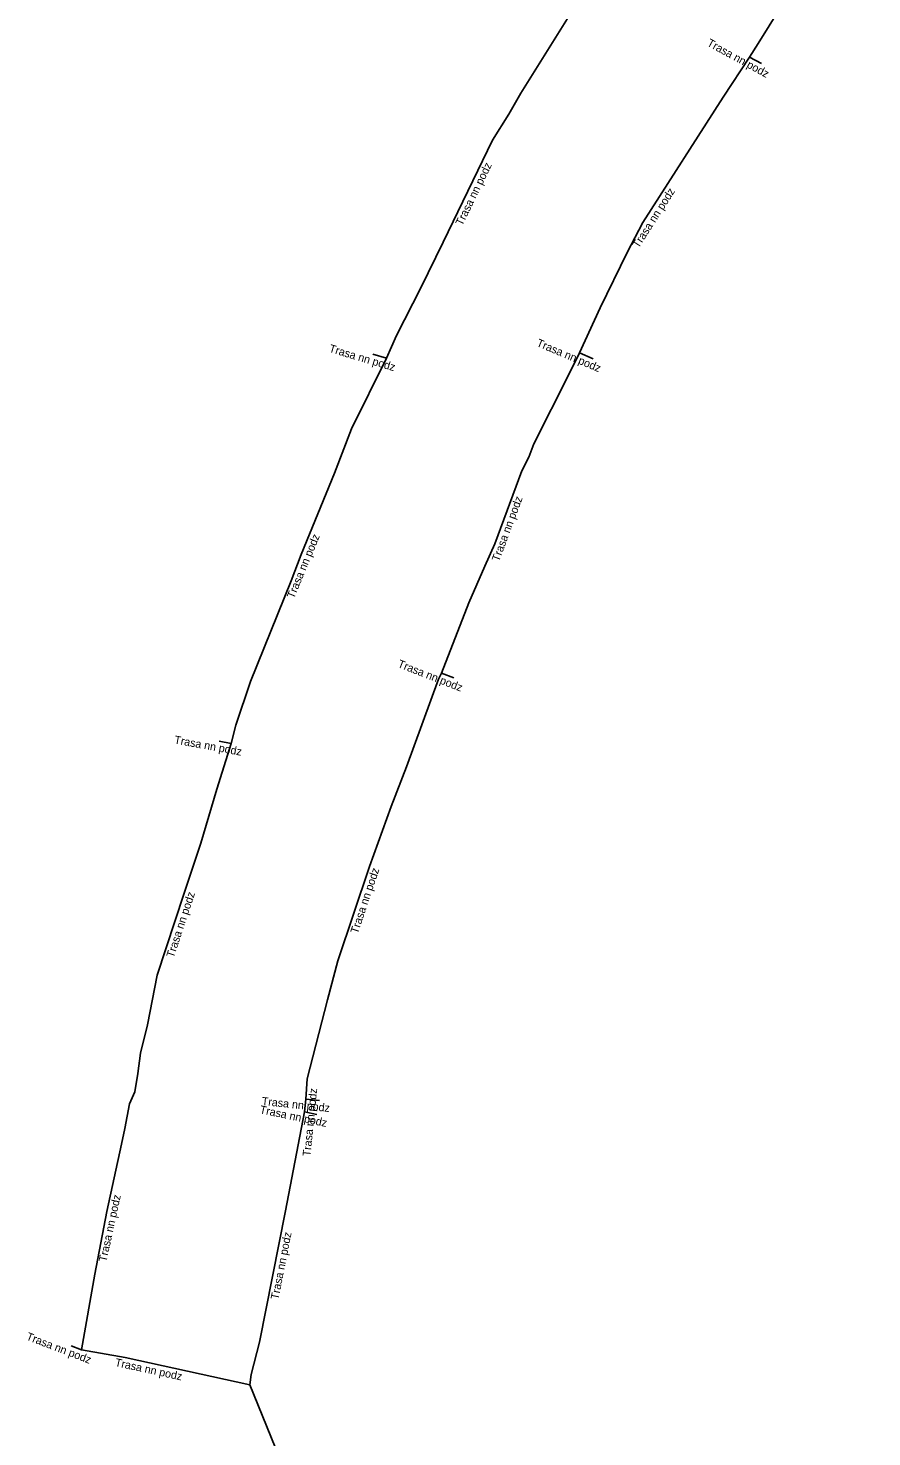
# Model space of a CAD drawing. Extents: x -756855 to -756032, y -1046964 to -1046550.
# Drawn here: x -756693.7 to -756641, y -1046811.5 to -1046723.5 of the extents above; entities that cross this region are included whole.
import ezdxf

# ---------------------------------------------------------------- set-up
doc = ezdxf.new("R2010")
doc.units = 0
doc.layers.add('Popiskový text - Ostatní atributy Trasy', color=7, linetype='Continuous')
doc.layers.add('Spojnice NN', color=7, linetype='Continuous')

msp = doc.modelspace()

# ---------------------------------------------------------------- linework, layer by layer
at = {"layer": 'Spojnice NN'}
for points in [[(-756648.65, -1046725.33), (-756648.11, -1046724.48), (-756646.73, -1046722.28), (-756645.19, -1046719.9), (-756641.81, -1046715.04), (-756641.2, -1046714.23), (-756641.01, -1046714.01)], [(-756671.34, -1046744.14), (-756670.71, -1046742.72), (-756669.18, -1046739.75), (-756667.8, -1046736.89), (-756664.71, -1046730.52), (-756663.69, -1046728.89), (-756663.19, -1046728.02), (-756662.95, -1046727.58), (-756659.41, -1046721.92)], [(-756659.28, -1046743.81), (-756657.99, -1046741), (-756656.3, -1046737.54), (-756655.31, -1046735.67), (-756650.3, -1046727.84), (-756648.65, -1046725.33)], [(-756648.65, -1046725.33), (-756647.906, -1046725.736)], [(-756681.03, -1046768.2), (-756680.75, -1046767.06), (-756679.83, -1046764.34), (-756677.3, -1046758.04), (-756676.67, -1046756.41), (-756674.58, -1046751.33), (-756673.52, -1046748.56), (-756671.34, -1046744.14)], [(-756672.18, -1046743.89), (-756671.34, -1046744.14)], [(-756667.89, -1046763.81), (-756666.19, -1046759.43), (-756665.19, -1046757.14), (-756664.57, -1046755.73), (-756662.88, -1046751.17), (-756662.44, -1046750.33), (-756662.12, -1046749.49), (-756659.95, -1046745.16), (-756659.28, -1046743.81)], [(-756659.28, -1046743.81), (-756658.421, -1046744.171)], [(-756676.38, -1046790.42), (-756676.3, -1046789.15), (-756675.03, -1046784.21), (-756674.37, -1046781.79), (-756672.4, -1046775.89), (-756671.04, -1046772.15), (-756670.08, -1046769.67), (-756668.09, -1046764.18), (-756667.89, -1046763.81)], [(-756667.89, -1046763.81), (-756667.125, -1046764.109)], [(-756686.86, -1046788.82), (-756686.71, -1046787.55), (-756686.26, -1046785.79), (-756685.66, -1046782.67), (-756683.99, -1046777.61), (-756682.94, -1046774.43), (-756681.94, -1046771.05), (-756681.03, -1046768.2)], [(-756681.03, -1046768.2), (-756681.79, -1046768.06)], [(-756686.86, -1046788.82), (-756687.06, -1046789.97), (-756687.39, -1046790.71), (-756687.69, -1046792.26), (-756687.9, -1046793.24), (-756688.81, -1046797.44), (-756689.55, -1046801.36), (-756690.38, -1046806.08)], [(-756676.46, -1046791.22), (-756676.38, -1046790.42)], [(-756676.38, -1046790.42), (-756675.514, -1046790.511)], [(-756679.87, -1046808.27), (-756679.79, -1046807.62), (-756679.27, -1046805.61), (-756677.65, -1046797.39), (-756676.46, -1046791.22)], [(-756676.46, -1046791.22), (-756675.682, -1046791.381)], [(-756690.38, -1046806.08), (-756691.043, -1046805.827)], [(-756690.38, -1046806.08), (-756687.66, -1046806.57), (-756679.87, -1046808.27)], [(-756679.87, -1046808.27), (-756677.74, -1046813.5), (-756675.76, -1046817.5), (-756672.52, -1046825.15), (-756668.11, -1046835.72), (-756665.75, -1046841.18), (-756663.24, -1046846.7), (-756660.56, -1046853.29), (-756658.44, -1046858.26)]]:
    msp.add_lwpolyline(points, dxfattribs=at)

# ---------------------------------------------------------------- texts
at = {"layer": 'Popiskový text - Ostatní atributy Trasy'}
for rotation, p in [(331.37875, (-756651.353, -1046724.596)), (64.12261, (-756666.6, -1046735.906)), (57.38699, (-756655.586, -1046737.307)), (343.42599, (-756674.962, -1046743.74)), (337.20512, (-756662.004, -1046743.37)), (69.66459, (-756664.303, -1046756.88)), (67.63689, (-756677.113, -1046759.196)), (338.65197, (-756670.676, -1046763.419)), (349.56252, (-756684.623, -1046768.199)), (71.53592, (-756673.129, -1046780.126)), (71.73507, (-756684.631, -1046781.626)), (84.28941, (-756676.086, -1046794.017)), (354.00133, (-756679.146, -1046790.783)), (348.3082, (-756679.285, -1046791.299)), (77.77488, (-756688.833, -1046800.617)), (78.85101, (-756678.087, -1046802.972)), (339.11321, (-756693.884, -1046805.438)), (347.68943, (-756688.329, -1046807.089))]:
    msp.add_text('Trasa nn podz', height=0.5, rotation=rotation, dxfattribs=at).set_placement(p)

doc.saveas('drawing.dxf')
